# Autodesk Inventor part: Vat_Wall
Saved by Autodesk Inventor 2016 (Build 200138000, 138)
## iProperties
Created: 2016-03
Part Number: Vat_Wall
Material: Generic
Document SubType Name: Modeling
Designer: bongo_000
Density: 1 g/cm^3
Appearance: Default
Author: bongo_000
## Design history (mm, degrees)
feature "SOLID1"
body "Solid1"
